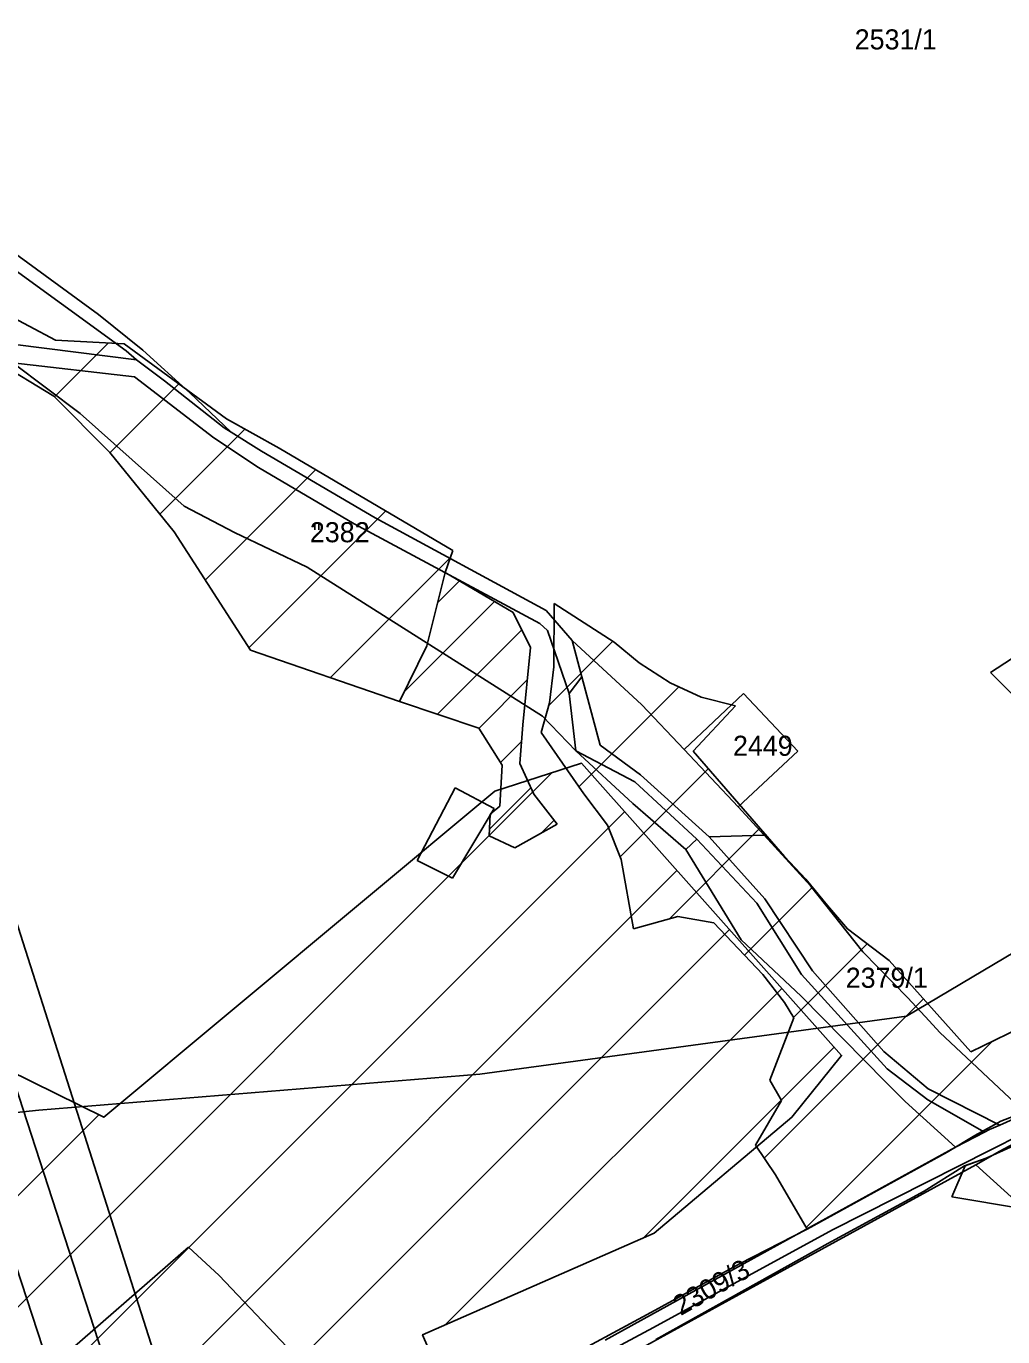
# Model space of a CAD drawing. Extents: x -564810 to -550519, y -1045831 to -1034011.
# Drawn here: x -552001 to -551752.9, y -1037775.2 to -1037442.3 of the extents above; entities that cross this region are included whole.
import ezdxf

# ---------------------------------------------------------------- set-up
doc = ezdxf.new("R2010")
doc.units = 0
for name, color, linetype in [('KN stav', 7, 'Continuous'), ('Lesní porost', 7, 'Continuous'), ('Odvodněné plochy', 7, 'Continuous'), ('Parcelní čísla', 7, 'Continuous'), ('přeložka st silnice', 7, 'Continuous'), ('STG', 7, 'Continuous'), ('Vedení VN', 7, 'Continuous'), ('vodní toky', 7, 'Continuous'), ('Vrstva 33', 7, 'Continuous'), ('Vrstva 4', 7, 'Continuous'), ('zamokř ploch', 7, 'Continuous')]:
    doc.layers.add(name, color=color, linetype=linetype)

msp = doc.modelspace()

# ---------------------------------------------------------------- linework, layer by layer
at = {"layer": 'KN stav'}
for p, q in [((-552015.17, -1037491.75), (-551982.62, -1037515.54)), ((-552018.5, -1037493.58), (-551975.61, -1037524.72)), ((-551982.62, -1037515.54), (-551971.36, -1037524.58)), ((-552003.81, -1037523.18), (-551972.96, -1037527.06)), ((-551975.61, -1037524.72), (-551972.96, -1037527.06)), ((-551971.36, -1037524.58), (-551959.39, -1037535.45)), ((-551973.47, -1037531.4), (-552004.36, -1037527.84)), ((-551987.25, -1037540.65), (-552004.36, -1037527.84)), ((-551972.96, -1037527.06), (-551965.87, -1037532.36)), ((-551953.3, -1037546.86), (-551973.47, -1037531.4)), ((-551965.87, -1037532.36), (-551950.69, -1037544.34)), ((-551959.39, -1037535.45), (-551948.93, -1037545.44)), ((-551960.88, -1037564.19), (-551987.25, -1037540.65)), ((-551950.69, -1037544.34), (-551948.93, -1037545.44)), ((-551948.93, -1037545.44), (-551941.17, -1037550.29)), ((-551941.97, -1037554.44), (-551953.3, -1037546.86)), ((-551941.17, -1037550.29), (-551912.28, -1037567.16)), ((-551917.64, -1037568.69), (-551941.97, -1037554.44)), ((-551948.04, -1037570.9), (-551960.88, -1037564.19)), ((-551870.47, -1037594.02), (-551917.64, -1037568.69)), ((-551912.28, -1037567.16), (-551868.91, -1037590.72)), ((-551929.62, -1037579.72), (-551948.04, -1037570.9)), ((-551869.8, -1037617.58), (-551929.62, -1037579.72)), ((-551868.91, -1037590.72), (-551862.31, -1037598.38)), ((-551755.97, -1037606.51), (-551732.83, -1037591.21)), ((-551868.5, -1037595.78), (-551870.47, -1037594.02)), ((-551862.99, -1037611.79), (-551868.5, -1037595.78)), ((-551862.31, -1037598.38), (-551859.85, -1037607.55)), ((-551862.31, -1037598.38), (-551844.6, -1037614.73)), ((-551859.85, -1037607.55), (-551862.99, -1037611.79)), ((-551741.48, -1037621), (-551755.97, -1037606.51)), ((-551862.99, -1037611.79), (-551861.37, -1037626.38)), ((-551833.85, -1037626.07), (-551818.73, -1037611.82)), ((-551818.73, -1037611.82), (-551804.97, -1037626.43)), ((-551844.6, -1037614.73), (-551833.85, -1037626.07)), ((-551861.37, -1037626.38), (-551869.8, -1037617.58)), ((-551846.86, -1037639.77), (-551861.37, -1037626.38)), ((-551820.07, -1037640.62), (-551833.85, -1037626.07)), ((-551804.97, -1037626.43), (-551820.07, -1037640.62)), ((-551846.86, -1037639.77), (-551833.35, -1037651.46)), ((-551820.07, -1037640.62), (-551813.48, -1037647.84)), ((-551813.48, -1037647.84), (-551801.75, -1037660.69)), ((-551833.35, -1037651.46), (-551819.37, -1037674.41)), ((-551801.75, -1037660.69), (-551788.41, -1037677.42)), ((-551819.37, -1037674.41), (-551815.3, -1037678.22)), ((-551815.3, -1037678.22), (-551804.1, -1037688.7)), ((-551788.41, -1037677.42), (-551777.01, -1037689.1)), ((-551804.1, -1037688.7), (-551782.65, -1037710.46)), ((-551777.01, -1037689.1), (-551771.59, -1037694.95)), ((-551771.59, -1037694.95), (-551768.83, -1037697.93)), ((-551768.83, -1037697.93), (-551747.1, -1037718.36)), ((-551777.7, -1037715.49), (-551782.65, -1037710.46)), ((-551764.88, -1037727.06), (-551777.7, -1037715.49)), ((-551753.63, -1037721.44), (-551756.21, -1037722.59)), ((-551750.23, -1037719.94), (-551753.63, -1037721.44)), ((-551757.47, -1037723.24), (-551764.88, -1037727.06)), ((-551756.21, -1037722.59), (-551757.47, -1037723.24)), ((-551764.88, -1037727.06), (-551802.89, -1037748)), ((-551759.69, -1037731.54), (-551753.62, -1037728.1)), ((-551753.62, -1037728.1), (-551749.94, -1037726.09)), ((-551802.36, -1037754.94), (-551759.69, -1037731.54)), ((-551743.48, -1037746.26), (-551759.69, -1037731.54)), ((-551802.89, -1037748), (-551853.88, -1037776.09)), ((-552000.45, -1037787.9), (-551959.74, -1037752.49)), ((-551959.74, -1037752.49), (-551951.91, -1037759.69)), ((-551802.36, -1037754.94), (-551849.45, -1037780.77)), ((-551951.91, -1037759.69), (-551929.81, -1037782.91))]:
    msp.add_line(p, q, dxfattribs=at)
at = {"layer": 'Lesní porost'}
for p, q in [((-551993.53, -1037522.03), (-552006.93, -1037514.9)), ((-551976.12, -1037523.02), (-551993.53, -1037522.03)), ((-552012.49, -1037525.04), (-551993.97, -1037536.29)), ((-551993.8, -1037536.46), (-551980.14, -1037522.79)), ((-551950.09, -1037542.05), (-551976.12, -1037523.02)), ((-551979.68, -1037550.62), (-551962.23, -1037533.17)), ((-551993.97, -1037536.29), (-551979.71, -1037550.58)), ((-551936.68, -1037549.45), (-551950.09, -1037542.05)), ((-551967.02, -1037566.24), (-551945.41, -1037544.63)), ((-551979.71, -1037550.58), (-551963.39, -1037570.72)), ((-551892.61, -1037575.45), (-551936.68, -1037549.45)), ((-551955.48, -1037582.99), (-551927.41, -1037554.92)), ((-551944.39, -1037600.18), (-551909.62, -1037565.41)), ((-551894.54, -1037581.04), (-551892.61, -1037575.45)), ((-551923.72, -1037607.8), (-551893.26, -1037577.33)), ((-551899.21, -1037599.67), (-551894.54, -1037581.04)), ((-551866.83, -1037588.98), (-551866.9, -1037605.05)), ((-551851.62, -1037598.73), (-551866.83, -1037588.98)), ((-551868.27, -1037614.92), (-551851.9, -1037598.55)), ((-551845.24, -1037604.02), (-551851.62, -1037598.73)), ((-551906.17, -1037613.88), (-551899.21, -1037599.67)), ((-551866.9, -1037605.05), (-551868.06, -1037614.16)), ((-551837.35, -1037609.13), (-551845.24, -1037604.02)), ((-551860.58, -1037635.51), (-551835.19, -1037610.13)), ((-551829.48, -1037612.77), (-551837.35, -1037609.13)), ((-551868.06, -1037614.16), (-551870.15, -1037621.74)), ((-551831.49, -1037626.45), (-551820.8, -1037614.92)), ((-551820.8, -1037614.92), (-551829.48, -1037612.77)), ((-551870.15, -1037621.74), (-551859.31, -1037637.34)), ((-551808.33, -1037653.25), (-551831.49, -1037626.45)), ((-551850.1, -1037653.32), (-551827.66, -1037630.88)), ((-551859.31, -1037637.34), (-551853.31, -1037645.22)), ((-551853.31, -1037645.22), (-551849.82, -1037654.02)), ((-551837.55, -1037669.05), (-551814.55, -1037646.05)), ((-551849.82, -1037654.02), (-551846.68, -1037671.6)), ((-551802.93, -1037658.99), (-551808.33, -1037653.25)), ((-551797.43, -1037665.67), (-551802.93, -1037658.99)), ((-551818.48, -1037678.26), (-551801.25, -1037661.03)), ((-551792.33, -1037671.56), (-551797.43, -1037665.67)), ((-551846.68, -1037671.6), (-551835.46, -1037668.47)), ((-551835.46, -1037668.47), (-551826.29, -1037670.03)), ((-551826.29, -1037670.03), (-551813.81, -1037683.18)), ((-551781.69, -1037679.68), (-551792.33, -1037671.56)), ((-551806.03, -1037694.1), (-551787.32, -1037675.39)), ((-551760.96, -1037702.81), (-551781.69, -1037679.68)), ((-551813.81, -1037683.18), (-551808.33, -1037690.32)), ((-551729.97, -1037687.69), (-551760.96, -1037702.81)), ((-551813.47, -1037729.82), (-551773.01, -1037689.36)), ((-551808.33, -1037690.32), (-551805.97, -1037694.19)), ((-551805.97, -1037694.19), (-551812.06, -1037710.03)), ((-551802.84, -1037747.48), (-551755.52, -1037700.15)), ((-551812.06, -1037710.03), (-551809.07, -1037715.17)), ((-551809.07, -1037715.17), (-551815.72, -1037726.55)), ((-551760, -1037724.07), (-551753.34, -1037720.45)), ((-551767.01, -1037728.36), (-551760, -1037724.07)), ((-551815.72, -1037726.55), (-551810.57, -1037734.05)), ((-551765.84, -1037739.68), (-551762.44, -1037731.84)), ((-551810.57, -1037734.05), (-551802.6, -1037747.89))]:
    msp.add_line(p, q, dxfattribs=at)
for points in [[(-551963.39, -1037570.72), (-551944.02, -1037600.76)], [(-551944.02, -1037600.76), (-551906.17, -1037613.88)], [(-551753.34, -1037720.45), (-551740.86, -1037715.63), (-551723.49, -1037706.18), (-551713.37, -1037701.07)], [(-551765.84, -1037739.68), (-551748.12, -1037742.61), (-551742.85, -1037747.34), (-551743.08, -1037730.72), (-551719.28, -1037732.6), (-551706.26, -1037729.39), (-551700, -1037729.51), (-551705.04, -1037727.2), (-551708.65, -1037724.18), (-551711.56, -1037715.54), (-551713.69, -1037707.08), (-551720.97, -1037710.45), (-551720.97, -1037710.45), (-551739.85, -1037720.4), (-551750.16, -1037726.73), (-551757.06, -1037729.83), (-551762.44, -1037731.84)], [(-551802.6, -1037747.89), (-551767.01, -1037728.36)]]:
    msp.add_lwpolyline(points, dxfattribs=at)
at = {"layer": 'Odvodněné plochy'}
msp.add_lwpolyline([(-552115.61, -1037653.21), (-551981.27, -1037719.48), (-551881.89, -1037636.64), (-551859.9, -1037629.55), (-551793.83, -1037703.77), (-551806.43, -1037719.48), (-551841.4, -1037748.93), (-551900.29, -1037774.7), (-551876.37, -1037829.93)], dxfattribs=at)
at = {"layer": 'přeložka st silnice'}
for p, q in [((-553031.34, -1038795.91), (-551867.4, -1037631.97)), ((-553022.09, -1038814.94), (-551848.97, -1037641.83)), ((-553012.83, -1038833.97), (-551835.65, -1037656.79)), ((-553003.58, -1038853), (-551822.33, -1037671.75)), ((-551894.44, -1037772.14), (-551809.01, -1037686.72)), ((-551844.14, -1037750.13), (-551795.69, -1037701.68)), ((-553026.22, -1038762.51), (-551982.56, -1037718.84))]:
    msp.add_line(p, q, dxfattribs=at)
at = {"layer": 'STG'}
msp.add_lwpolyline([(-552085.98, -1037726.88), (-551997.79, -1037717.69), (-551885.73, -1037708.5), (-551777.34, -1037693.8), (-551650.58, -1037618.46), (-551597.31, -1037544.96), (-551593.63, -1037467.78), (-551597.31, -1037397.95), (-551586.28, -1037311.58), (-551545.87, -1037245.43), (-551516.47, -1037186.63), (-551459.52, -1037149.88), (-551378.69, -1037116.8), (-551273.98, -1037100.26), (-551202.33, -1037076.37), (-551108.64, -1037028.6), (-550987.39, -1036980.82), (-550890.39, -1036925.69), (-550831.6, -1036883.43), (-550758.12, -1036817.27), (-550710.36, -1036749.28), (-550693.82, -1036703.34), (-550693.82, -1036639.03), (-550758.12, -1036504.88)], dxfattribs=at)
at = {"layer": 'Vedení VN'}
for points in [[(-552432.62, -1036280.68), (-552381.75, -1036354.88), (-552340.78, -1036472.89), (-552289.91, -1036771.81), (-551953.63, -1037825.94), (-551890.75, -1037944.66), (-551680.22, -1038317.07)], [(-551695.24, -1038326.94), (-551700.71, -1038330.65), (-551972.06, -1037853.73), (-552325.94, -1036770.4), (-552370.45, -1036480.66), (-552411.81, -1036369.59), (-552471.47, -1036287.75)], [(-551691.6, -1038324.25), (-551753.32, -1038215.22), (-551815.56, -1038104.9), (-551888.03, -1037977.11), (-551957.29, -1037854.44), (-552010.26, -1037691.39), (-552038.99, -1037602.42), (-552068.06, -1037512.55)]]:
    msp.add_lwpolyline(points, dxfattribs=at)
at = {"layer": 'vodní toky'}
msp.add_lwpolyline([(-551841.01, -1037775.91), (-551797.34, -1037751.57), (-551772.81, -1037738.22), (-551762.55, -1037731.81), (-551757.06, -1037729.83), (-551750.16, -1037726.73), (-551739.85, -1037720.4), (-551720.97, -1037710.45), (-551713.69, -1037707.08), (-551711.78, -1037704.93), (-551712.17, -1037703.92), (-551713.37, -1037701.07), (-551723.49, -1037706.18), (-551740.86, -1037715.63), (-551753.34, -1037720.45), (-551759.89, -1037724.09), (-551767.01, -1037728.36), (-551802.6, -1037747.89), (-551819.78, -1037756.67), (-551841.14, -1037768.44), (-551881.5, -1037790.23)], dxfattribs=at)
at = {"layer": 'Vrstva 33'}
msp.add_lwpolyline([(-551707.95, -1037703.51), (-551796.1, -1037748.03), (-551841.58, -1037772.91), (-551912.77, -1037811.01), (-551947.88, -1037830.27), (-551968.23, -1037855.25), (-551986.23, -1037865.71), (-552006.06, -1037866.84)], dxfattribs=at)
at = {"layer": 'Vrstva 4'}
for p, q in [((-551859.85, -1037607.55), (-551855.18, -1037624.97)), ((-551855.18, -1037624.97), (-551844.87, -1037632.49)), ((-551846.38, -1037634.25), (-551861.37, -1037626.38)), ((-551830.63, -1037648.78), (-551846.38, -1037634.25)), ((-551844.87, -1037632.49), (-551827.5, -1037648.24)), ((-551901.63, -1037654.22), (-551891.97, -1037635.74)), ((-551891.97, -1037635.74), (-551882.06, -1037640.99)), ((-551882.06, -1037640.99), (-551892.66, -1037658.74)), ((-551833.35, -1037651.46), (-551830.63, -1037648.78)), ((-551830.63, -1037648.78), (-551815.35, -1037665.11)), ((-551827.5, -1037648.24), (-551813.48, -1037647.83)), ((-551827.5, -1037648.24), (-551813.3, -1037664.01)), ((-551892.66, -1037658.74), (-551901.63, -1037654.22)), ((-551815.35, -1037665.11), (-551804, -1037683.18)), ((-551813.3, -1037664.01), (-551801.23, -1037682.24)), ((-551801.23, -1037682.24), (-551783.05, -1037702.76)), ((-551804, -1037683.18), (-551782.2, -1037707.15)), ((-551783.05, -1037702.76), (-551771.8, -1037712.21)), ((-551782.2, -1037707.15), (-551771.93, -1037715.01)), ((-551771.8, -1037712.21), (-551753.63, -1037721.44)), ((-551771.93, -1037715.01), (-551757.47, -1037723.23))]:
    msp.add_line(p, q, dxfattribs=at)
at = {"layer": 'zamokř ploch'}
for p, q in [((-551927.66, -1037568.77), (-551927.66, -1037570.27)), ((-551926.66, -1037568.77), (-551926.66, -1037570.27)), ((-551894.54, -1037581.04), (-551899.21, -1037599.67)), ((-551877.22, -1037591.23), (-551894.54, -1037581.04)), ((-551896.47, -1037588.76), (-551890.9, -1037583.18)), ((-551904.94, -1037611.36), (-551881.99, -1037588.42)), ((-551872.84, -1037600.11), (-551877.22, -1037591.23)), ((-551896.52, -1037617.09), (-551875.05, -1037595.62)), ((-551899.21, -1037599.67), (-551906.17, -1037613.88)), ((-551874.82, -1037619.78), (-551872.84, -1037600.11)), ((-551885.92, -1037620.63), (-551873.67, -1037608.38)), ((-551906.17, -1037613.88), (-551885.94, -1037620.61)), ((-551885.94, -1037620.61), (-551880.07, -1037629.98)), ((-551875.56, -1037629.6), (-551874.82, -1037619.78)), ((-551880.48, -1037629.33), (-551875.14, -1037623.99)), ((-551880.07, -1037629.98), (-551880.68, -1037640.4)), ((-551871.97, -1037637.42), (-551875.56, -1037629.6)), ((-551883.25, -1037646.25), (-551872.74, -1037635.74)), ((-551866.04, -1037645), (-551871.97, -1037637.42)), ((-551880.68, -1037640.4), (-551883.1, -1037642.47)), ((-551883.1, -1037642.47), (-551883.32, -1037647.93)), ((-551876.84, -1037650.98), (-551866.04, -1037645)), ((-551870.13, -1037647.26), (-551866.84, -1037643.98)), ((-551883.32, -1037647.93), (-551876.84, -1037650.98))]:
    msp.add_line(p, q, dxfattribs=at)

# ---------------------------------------------------------------- texts
at = {"layer": 'Parcelní čísla'}
for s, p in [('2531/1', (-551790.49, -1037448.19)), ('2382', (-551928.91, -1037573.39)), ('2449', (-551821.41, -1037627.64)), ('2379/1', (-551792.77, -1037686.57))]:
    msp.add_text(s, height=5.1, dxfattribs=at).set_placement(p)
msp.add_text('2309/3', height=5.1, rotation=29.6831, dxfattribs=at).set_placement((-551834.71, -1037769.99))

doc.saveas('drawing.dxf')
